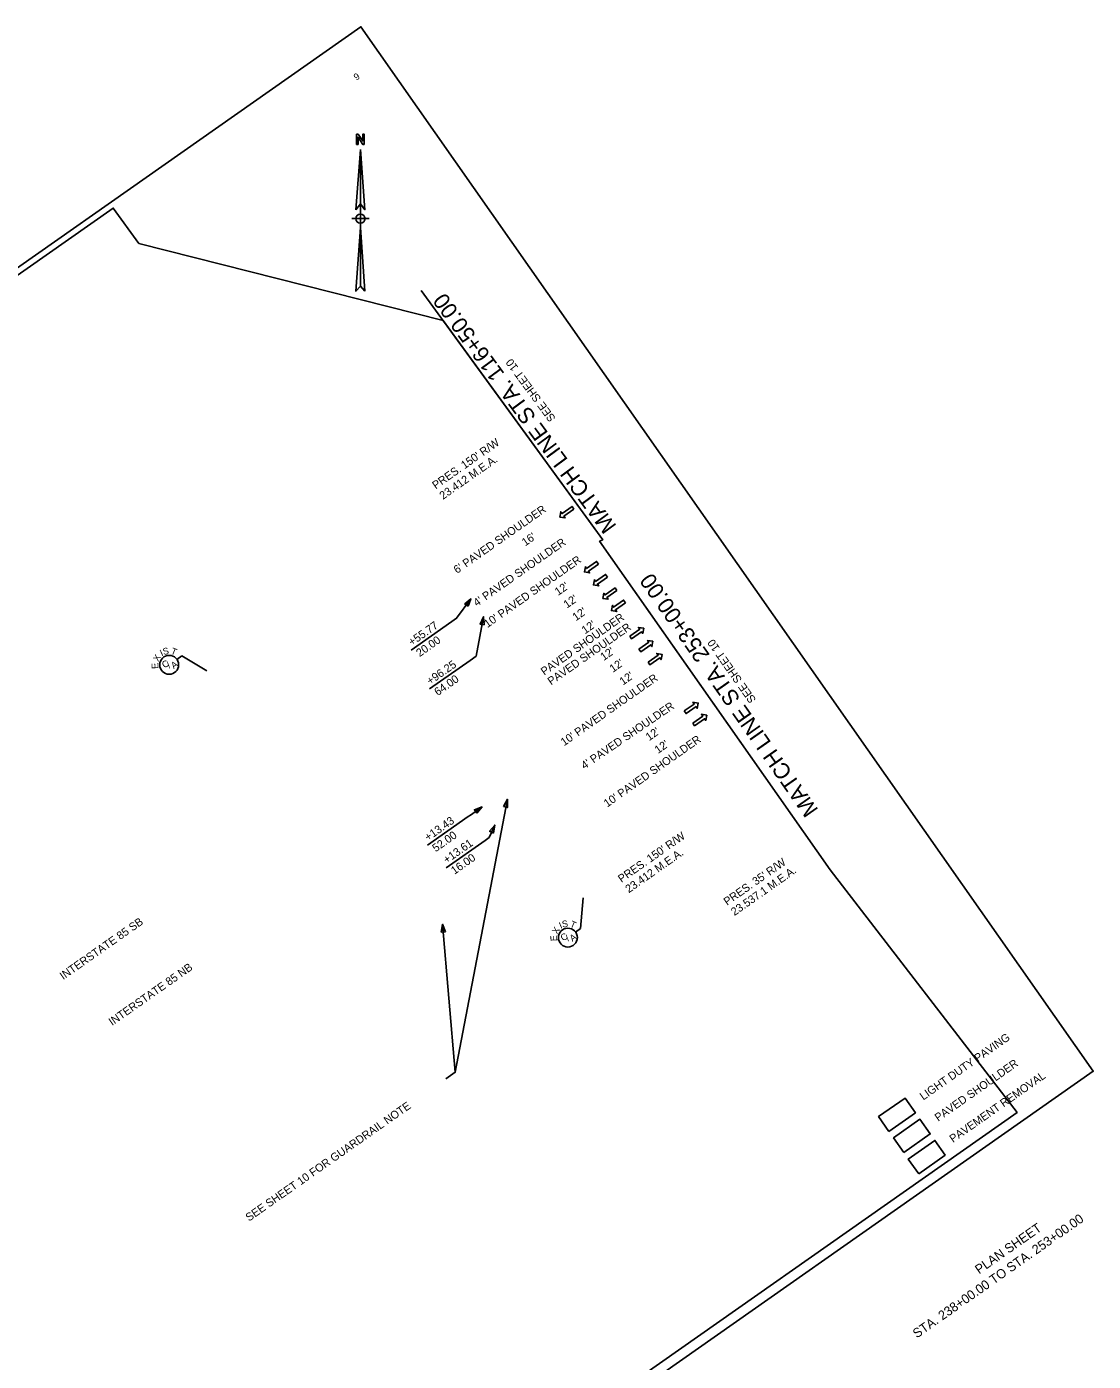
# Model space of a CAD drawing. Extents: x 1606191 to 1608111, y 1090371 to 1092208.
# Drawn here: x 1607311 to 1608111, y 1091146 to 1092146 of the extents above; entities that cross this region are included whole.
import ezdxf

# ---------------------------------------------------------------- set-up
doc = ezdxf.new("R2010")
doc.units = 0
for name, color, linetype in [('Copy of RD_HC_SUR_CL200', 7, 'Continuous'), ('Copy of RD_HC_SUR_DATA_200', 7, 'Continuous'), ('RD_EX_BldgApp', 7, 'Continuous'), ('RD_EX_Fence_Other', 7, 'Continuous'), ('RD_EX_Misc', 7, 'Continuous'), ('RD_EX_Misc_Golf_Teebox', 7, 'Continuous'), ('RD_EX_RailRoad', 7, 'Continuous'), ('RD_EX_TopoTX', 7, 'Continuous'), ('RD_EX_VEG', 7, 'Continuous'), ('V-BLDG-OTLN', 7, 'Continuous')]:
    doc.layers.add(name, color=color, linetype=linetype)

msp = doc.modelspace()

# ---------------------------------------------------------------- linework, layer by layer
at = {"layer": 'Copy of RD_HC_SUR_CL200'}
for p, q in [((1607424.1, 1091671.9), (1607427.8, 1091674.5)), ((1607427.8, 1091674.5), (1607446.6, 1091663.3)), ((1607726.8, 1091470), (1607728.8, 1091493.2)), ((1607723.1, 1091467.3), (1607726.8, 1091470))]:
    msp.add_line(p, q, dxfattribs=at)
for centre in [(1607418.3, 1091667.8), (1607717.3, 1091463.3)]:
    msp.add_circle(centre, 7.08, dxfattribs=at)
at = {"layer": 'Copy of RD_HC_SUR_DATA_200'}
msp.add_line((1607632.8, 1091362.4), (1607672, 1091567), dxfattribs=at)
for points in [[(1607669.1, 1091561.6), (1607672, 1091567), (1607672, 1091560.8)], [(1607625.4, 1091467.6), (1607623.3, 1091473.3), (1607622.3, 1091467.4)]]:
    msp.add_lwpolyline(points, close=True, dxfattribs=at)
msp.add_lwpolyline([(1607625.8, 1091357.4), (1607632.8, 1091362.4), (1607623.3, 1091473.3)], dxfattribs=at)
at = {"layer": 'RD_EX_Fence_Other'}
msp.add_lwpolyline([(1606190.8, 1091184.3), (1607562.1, 1092146.2), (1608111.3, 1091363.1), (1606740.1, 1090401.3)], close=True, dxfattribs=at)
at = {"layer": 'RD_EX_Misc'}
for points in [[(1607721.8, 1091784.5), (1607720.4, 1091786.5), (1607712.9, 1091781.2), (1607711.9, 1091782.5), (1607711.3, 1091778.6), (1607715.2, 1091777.9), (1607714.3, 1091779.2)], [(1607740.2, 1091743.3), (1607738.8, 1091745.3), (1607731.3, 1091740), (1607730.4, 1091741.3), (1607729.7, 1091737.4), (1607733.6, 1091736.7), (1607732.7, 1091738)], [(1607747, 1091733.6), (1607745.6, 1091735.6), (1607738.1, 1091730.3), (1607737.2, 1091731.6), (1607736.5, 1091727.7), (1607740.4, 1091727), (1607739.5, 1091728.3)], [(1607754.1, 1091723.5), (1607752.7, 1091725.5), (1607745.2, 1091720.2), (1607744.2, 1091721.5), (1607743.6, 1091717.6), (1607747.5, 1091716.9), (1607746.6, 1091718.2)], [(1607760.5, 1091714.3), (1607759.1, 1091716.3), (1607751.6, 1091711), (1607750.7, 1091712.4), (1607750, 1091708.4), (1607753.9, 1091707.7), (1607753, 1091709.1)], [(1607763.7, 1091689.3), (1607765, 1091687.4), (1607772.5, 1091692.6), (1607773.5, 1091691.3), (1607774.2, 1091695.2), (1607770.2, 1091695.9), (1607771.2, 1091694.6)], [(1607770.5, 1091679.5), (1607771.9, 1091677.6), (1607779.4, 1091682.8), (1607780.3, 1091681.5), (1607781, 1091685.5), (1607777.1, 1091686.1), (1607778, 1091684.8)], [(1607777.4, 1091669.7), (1607778.8, 1091667.7), (1607786.3, 1091673), (1607787.2, 1091671.7), (1607787.9, 1091675.6), (1607784, 1091676.3), (1607784.9, 1091675)], [(1607804.5, 1091633.2), (1607805.9, 1091631.2), (1607813.4, 1091636.5), (1607814.3, 1091635.1), (1607815, 1091639.1), (1607811.1, 1091639.8), (1607812, 1091638.4)], [(1607810.9, 1091624.1), (1607812.3, 1091622.1), (1607819.8, 1091627.4), (1607820.7, 1091626.1), (1607821.4, 1091630), (1607817.4, 1091630.7), (1607818.4, 1091629.4)]]:
    msp.add_lwpolyline(points, close=True, dxfattribs=at)
at = {"layer": 'RD_EX_Misc_Golf_Teebox'}
for p, q in [((1607630.3, 1091700.3), (1607599.8, 1091678.9)), ((1607644, 1091671.1), (1607613.5, 1091649.7)), ((1607642.4, 1091554), (1607611.9, 1091532.6)), ((1607655.2, 1091536.2), (1607625.9, 1091515.7))]:
    msp.add_line(p, q, dxfattribs=at)
for points in [[(1607630.3, 1091700.3), (1607633.8, 1091702.7), (1607644.6, 1091717.2)], [(1607644, 1091671.1), (1607648.6, 1091674.3), (1607654.1, 1091703.8)], [(1607642.4, 1091554), (1607644.2, 1091555.2), (1607652.9, 1091561.3)], [(1607655.2, 1091536.2), (1607658.2, 1091538.3), (1607662.5, 1091547.6)], [(1607958, 1091318), (1607977.9, 1091332), (1607970.2, 1091343), (1607950.3, 1091329.1), (1607958, 1091318)], [(1607969.2, 1091302.1), (1607989.1, 1091316.1), (1607981.3, 1091327.1), (1607961.5, 1091313.1), (1607969.2, 1091302.1)], [(1607980.4, 1091286.2), (1608000.2, 1091300.2), (1607992.5, 1091311.2), (1607972.6, 1091297.2), (1607980.4, 1091286.2)]]:
    msp.add_lwpolyline(points, dxfattribs=at)
for points in [[(1607642.4, 1091711.7), (1607644.6, 1091717.2), (1607639.9, 1091713.5)], [(1607654.5, 1091697.8), (1607654.1, 1091703.8), (1607651.5, 1091698.4)], [(1607649, 1091556.7), (1607652.9, 1091561.3), (1607647.2, 1091559.2)], [(1607661.4, 1091541.7), (1607662.5, 1091547.6), (1607658.6, 1091543)], [(1607958, 1091318), (1607977.9, 1091332), (1607970.2, 1091343), (1607950.3, 1091329.1)], [(1607969.2, 1091302.1), (1607989.1, 1091316.1), (1607981.3, 1091327.1), (1607961.5, 1091313.1)], [(1607980.4, 1091286.2), (1608000.2, 1091300.2), (1607992.5, 1091311.2), (1607972.6, 1091297.2)]]:
    msp.add_lwpolyline(points, close=True, dxfattribs=at)
at = {"layer": 'RD_EX_RailRoad'}
for p, q in [((1607561.7, 1092054.2), (1607558.3, 1092008.9)), ((1607561.7, 1092013.5), (1607558.3, 1092008.9)), ((1607561.7, 1092013.5), (1607561.7, 1091995.7)), ((1607568.2, 1092002.3), (1607555.2, 1092002.3)), ((1607561.7, 1091995.7), (1607565.1, 1091947.9)), ((1607565.1, 1091947.9), (1607561.7, 1091951.7))]:
    msp.add_line(p, q, dxfattribs=at)
msp.add_lwpolyline([(1607564.6, 1092058), (1607563.4, 1092058), (1607560, 1092063.5), (1607560, 1092062.7), (1607560, 1092058), (1607558.8, 1092058), (1607558.8, 1092065.6), (1607560, 1092065.6), (1607563.4, 1092060.6), (1607563.4, 1092061), (1607563.4, 1092065.6), (1607564.6, 1092065.6), (1607564.6, 1092058)], dxfattribs=at)
for points in [[(1607561.7, 1092054.2), (1607565.1, 1092008.9), (1607561.7, 1092013.5)], [(1607561.7, 1091995.7), (1607561.7, 1091951.7), (1607558.3, 1091947.9)]]:
    msp.add_lwpolyline(points, close=True, dxfattribs=at)
msp.add_circle((1607561.7, 1092002.3), 3.45, dxfattribs=at)
at = {"layer": 'RD_EX_VEG'}
msp.add_line((1607743.5, 1091761.6), (1607607.3, 1091948.5), dxfattribs=at)
msp.add_lwpolyline([(1607913.9, 1091514), (1607775.7, 1091711), (1607741.1, 1091760.4)], dxfattribs=at)
at = {"layer": 'V-BLDG-OTLN'}
msp.add_lwpolyline([(1606406.7, 1091049.1), (1606535.9, 1090871.8), (1606533, 1090870.5), (1606692.3, 1090643.6), (1606817.6, 1090464.9), (1608054.2, 1091332.3), (1607913.9, 1091514), (1607741.1, 1091760.4), (1607743.5, 1091761.6), (1607623.7, 1091926), (1607395.6, 1091983.6), (1607376.3, 1092010.2), (1606278.9, 1091240.8)], close=True, dxfattribs=at)
msp.add_lwpolyline([(1606406.7, 1091049.1), (1606535.9, 1090871.8), (1606533, 1090870.5), (1606692.3, 1090643.6), (1606817.6, 1090464.9), (1608054.2, 1091332.3), (1607913.9, 1091514), (1607741.1, 1091760.4), (1607743.5, 1091761.6), (1607623.7, 1091926), (1607395.6, 1091983.6), (1607376.3, 1092010.2), (1606278.9, 1091240.8)], close=True, dxfattribs=at)

# ---------------------------------------------------------------- texts
at = {"layer": 'Copy of RD_HC_SUR_CL200'}
for s, rotation, p in [('I', 24.9789, (1607412.7, 1091674.1)), ('S', 13.2584, (1607414.1, 1091675.1)), ('T', 338.0969, (1607419.1, 1091676.2)), ('E', 93.6275, (1607410.3, 1091664.9)), ('X', 60.1403, (1607410.1, 1091669.8)), ('C', 35.0436, (1607414.9, 1091665)), ('/', 35.0436, (1607418.5, 1091665)), ('A', 35.0436, (1607421.7, 1091664.5)), ('X', 58.1882, (1607709.2, 1091465.5)), ('I', 23.0267, (1607711.9, 1091469.8)), ('S', 11.3062, (1607713.4, 1091470.7)), ('T', 336.1448, (1607718.4, 1091471.6)), ('E', 91.6753, (1607709.3, 1091460.7)), ('C', 35.0436, (1607713.9, 1091460.4)), ('/', 35.0436, (1607717.6, 1091460.4)), ('A', 35.0436, (1607720.7, 1091460))]:
    msp.add_text(s, height=5, rotation=rotation, dxfattribs=at).set_placement(p)
at = {"layer": 'Copy of RD_HC_SUR_DATA_200'}
msp.add_text('SEE SHEET 10 FOR GUARDRAIL NOTE', height=6, rotation=35.0468, dxfattribs=at).set_placement((1607478.2, 1091250.3))
at = {"layer": 'RD_EX_BldgApp'}
for s, p in [("PRES. 150' R/W", (1607618.2, 1091799.2)), ('23.412 M.E.A.', (1607623.6, 1091791.4)), ("PRES. 150' R/W", (1607757.5, 1091504.2)), ('23.412 M.E.A.', (1607763, 1091496.5)), ("PRES. 35' R/W", (1607836.7, 1091487.1)), ('23.537.1 M.E.A.', (1607842.2, 1091479.4))]:
    msp.add_text(s, height=6, rotation=35.0468, dxfattribs=at).set_placement(p)
at = {"layer": 'RD_EX_Misc_Golf_Teebox'}
for s, height, rotation, p in [('9', 5, 35.0468, (1607558.8, 1092105.7)), ("6' PAVED SHOULDER", 6, 35.0181, (1607634.2, 1091735.9)), ("4' PAVED SHOULDER", 6, 35.0181, (1607649, 1091711.2)), ("16'", 6, 34.9948, (1607685.3, 1091756.5)), ("10' PAVED SHOULDER", 6, 35.1629, (1607657, 1091695.3)), ("12'", 6, 35.0535, (1607710, 1091719.4)), ("12'", 6, 35.0535, (1607716.6, 1091709.9)), ("12'", 6, 35.0535, (1607723.3, 1091700.4)), ('+55.77', 6, 35.0468, (1607600.3, 1091681.7)), ('PAVED SHOULDER', 6, 35.0452, (1607699.6, 1091659.6)), ('PAVED SHOULDER', 6, 35.0452, (1607704.7, 1091652.3)), ("12'", 6, 35.0535, (1607730.2, 1091690.6)), ('20.00', 6, 35.0468, (1607606.1, 1091673.5)), ("12'", 6, 35.0535, (1607744.2, 1091670.6)), ('+96.25', 6, 35.0468, (1607614, 1091652.5)), ("12'", 6, 35.0468, (1607751.1, 1091661.8)), ('64.00', 6, 35.0468, (1607619.7, 1091644.3)), ("10' PAVED SHOULDER", 6, 35.1629, (1607714.5, 1091606.7)), ("12'", 6, 35.0468, (1607758.6, 1091652.2)), ("4' PAVED SHOULDER", 6, 34.2893, (1607729.7, 1091589.2)), ("12'", 6, 35.0468, (1607778.2, 1091610.5)), ("10' PAVED SHOULDER", 6, 35.1629, (1607746.8, 1091560.7)), ("12'", 6, 35.0468, (1607784.9, 1091600.9)), ('+13.43', 6, 35.0468, (1607612.4, 1091535.4)), ('52.00', 6, 35.0468, (1607618.2, 1091527.2)), ('+13.61', 6, 35.0468, (1607626.4, 1091518.5)), ('16.00', 6, 35.0468, (1607632.2, 1091510.3)), ('LIGHT DUTY PAVING', 6, 35.0468, (1607983.8, 1091341.1)), ('PAVED SHOULDER', 6, 35.0468, (1607995, 1091325.2)), ('PAVEMENT REMOVAL', 6, 35.0468, (1608006.1, 1091309.3))]:
    msp.add_text(s, height=height, rotation=rotation, dxfattribs=at).set_placement(p)
at = {"layer": 'RD_EX_TopoTX'}
for s, height, rotation, p in [('INTERSTATE 85 SB', 6, 35.0535, (1607338.8, 1091431.4)), ('INTERSTATE 85 NB', 6, 35.0535, (1607375.5, 1091397)), ('STA. 238+00.00 TO STA. 253+00.00', 6.983, 35.0468, (1607979, 1091162.7)), ('PLAN SHEET', 6.98, 35.0468, (1608025.7, 1091210.7))]:
    msp.add_text(s, height=height, rotation=rotation, dxfattribs=at).set_placement(p)
at = {"layer": 'RD_EX_VEG'}
for s, height, rotation, p in [('MATCH LINE STA. 116+50.00', 12, 126.33, (1607754.2, 1091771.9)), ('SEE SHEET 10', 6, 126.3812, (1607708.4, 1091852.7)), ('MATCH LINE STA. 253+00.00', 12, 125.0468, (1607905.5, 1091559.1)), ('SEE SHEET 10', 6, 125.0981, (1607858.7, 1091641.7))]:
    msp.add_text(s, height=height, rotation=rotation, dxfattribs=at).set_placement(p)

doc.saveas('drawing.dxf')
